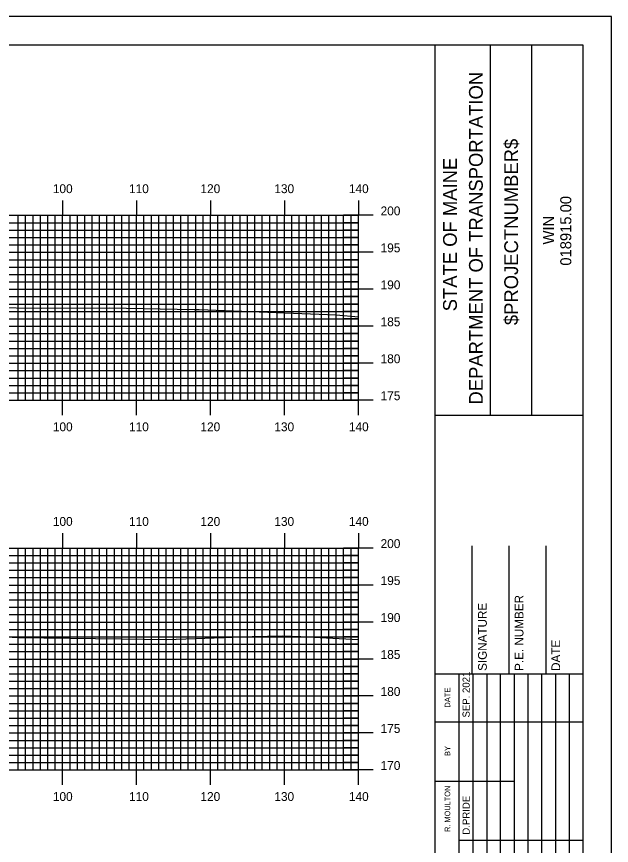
# Model space of a CAD drawing. Extents: x 1797207 to 1797550, y 442591 to 442811.
# Drawn here: x 1797466.7 to 1797547.1, y 442698.5 to 442810.5 of the extents above; entities that cross this region are included whole.
import ezdxf

# ---------------------------------------------------------------- set-up
doc = ezdxf.new("R2010")
doc.units = 0
for name, color, linetype in [('BORDER', 7, 'Continuous'), ('H_V ANNOTATION', 7, 'Continuous'), ('MAJOR', 7, 'Continuous'), ('MINOR', 7, 'Continuous'), ('PLOT BOUNDARY', 7, 'Continuous'), ('S_Roadway_Centerline', 7, 'Continuous')]:
    doc.layers.add(name, color=color, linetype=linetype)

msp = doc.modelspace()

# ---------------------------------------------------------------- linework, layer by layer
at = {"layer": 'BORDER'}
for p, q in [((1797523.33, 442596.67), (1797523.33, 442806.67)), ((1797530.79, 442756.66), (1797530.79, 442806.66)), ((1797536.38, 442756.66), (1797536.38, 442806.66)), ((1797523.33, 442756.65), (1797543.33, 442756.65)), ((1797528.33, 442721.67), (1797528.33, 442738.97)), ((1797533.33, 442721.67), (1797533.33, 442738.97)), ((1797538.33, 442721.67), (1797538.33, 442738.97)), ((1797523.33, 442721.67), (1797543.33, 442721.67))]:
    msp.add_line(p, q, dxfattribs=at)
msp.add_lwpolyline([(1797223.33, 442596.67), (1797543.33, 442596.67), (1797543.33, 442806.67), (1797223.33, 442806.67)], close=True, dxfattribs=at)
for points in [[(1797526.56, 442715.17), (1797526.56, 442721.67)], [(1797528.43, 442686.68), (1797528.43, 442721.67)], [(1797530.29, 442721.67), (1797530.29, 442686.68)], [(1797532.15, 442686.68), (1797532.15, 442721.67)], [(1797534.02, 442686.68), (1797534.02, 442721.67)], [(1797535.88, 442686.68), (1797535.88, 442721.67)], [(1797537.74, 442686.68), (1797537.74, 442721.67)], [(1797539.61, 442686.68), (1797539.61, 442721.67)], [(1797541.47, 442686.68), (1797541.47, 442721.67)], [(1797526.56, 442686.68), (1797526.56, 442720.26)], [(1797523.33, 442715.17), (1797543.33, 442715.17)], [(1797523.33, 442707.17), (1797526.56, 442707.17)], [(1797526.56, 442707.17), (1797534.01, 442707.17)], [(1797526.56, 442699.17), (1797543.33, 442699.17)]]:
    msp.add_lwpolyline(points, dxfattribs=at)
at = {"layer": 'MAJOR'}
for p, q in [((1797472.93, 442785.67), (1797472.93, 442783.67)), ((1797482.93, 442785.67), (1797482.93, 442783.67)), ((1797492.93, 442785.67), (1797492.93, 442783.67)), ((1797502.93, 442785.67), (1797502.93, 442783.67)), ((1797512.93, 442785.67), (1797512.93, 442783.67)), ((1797232.93, 442783.67), (1797512.93, 442783.67)), ((1797232.93, 442783.67), (1797512.93, 442783.67)), ((1797472.93, 442758.67), (1797472.93, 442783.67)), ((1797482.93, 442758.67), (1797482.93, 442783.67)), ((1797492.93, 442758.67), (1797492.93, 442783.67)), ((1797502.93, 442758.67), (1797502.93, 442783.67)), ((1797514.94, 442783.67), (1797510.93, 442783.67)), ((1797512.93, 442758.67), (1797512.93, 442783.67)), ((1797512.93, 442758.67), (1797512.93, 442783.67)), ((1797232.93, 442778.67), (1797512.93, 442778.67)), ((1797514.94, 442778.67), (1797510.93, 442778.67)), ((1797232.93, 442773.67), (1797512.93, 442773.67)), ((1797514.94, 442773.67), (1797510.93, 442773.67)), ((1797232.93, 442768.67), (1797512.93, 442768.67)), ((1797514.94, 442768.67), (1797510.93, 442768.67)), ((1797232.93, 442763.67), (1797512.93, 442763.67)), ((1797514.94, 442763.67), (1797510.93, 442763.67)), ((1797232.93, 442758.67), (1797512.93, 442758.67)), ((1797232.93, 442758.67), (1797512.93, 442758.67)), ((1797472.93, 442756.66), (1797472.93, 442758.67)), ((1797482.93, 442756.66), (1797482.93, 442758.67)), ((1797492.93, 442756.66), (1797492.93, 442758.67)), ((1797502.93, 442756.66), (1797502.93, 442758.67)), ((1797514.94, 442758.67), (1797510.93, 442758.67)), ((1797512.93, 442756.66), (1797512.93, 442758.67)), ((1797472.93, 442740.67), (1797472.93, 442738.67)), ((1797482.93, 442740.67), (1797482.93, 442738.67)), ((1797492.93, 442740.67), (1797492.93, 442738.67)), ((1797502.93, 442740.67), (1797502.93, 442738.67)), ((1797512.93, 442740.67), (1797512.93, 442738.67)), ((1797232.93, 442738.67), (1797512.93, 442738.67)), ((1797232.93, 442738.67), (1797512.93, 442738.67)), ((1797472.93, 442708.67), (1797472.93, 442738.67)), ((1797482.93, 442708.67), (1797482.93, 442738.67)), ((1797492.93, 442708.67), (1797492.93, 442738.67)), ((1797502.93, 442708.67), (1797502.93, 442738.67)), ((1797514.94, 442738.67), (1797510.93, 442738.67)), ((1797512.93, 442708.67), (1797512.93, 442738.67)), ((1797512.93, 442708.67), (1797512.93, 442738.67)), ((1797232.93, 442733.67), (1797512.93, 442733.67)), ((1797514.94, 442733.67), (1797510.93, 442733.67)), ((1797232.93, 442728.67), (1797512.93, 442728.67)), ((1797514.94, 442728.67), (1797510.93, 442728.67)), ((1797232.93, 442723.67), (1797512.93, 442723.67)), ((1797514.94, 442723.67), (1797510.93, 442723.67)), ((1797232.93, 442718.67), (1797512.93, 442718.67)), ((1797514.94, 442718.67), (1797510.93, 442718.67)), ((1797232.93, 442713.67), (1797512.93, 442713.67)), ((1797514.94, 442713.67), (1797510.93, 442713.67)), ((1797232.93, 442708.67), (1797512.93, 442708.67)), ((1797232.93, 442708.67), (1797512.93, 442708.67)), ((1797472.93, 442706.66), (1797472.93, 442708.67)), ((1797482.93, 442706.66), (1797482.93, 442708.67)), ((1797492.93, 442706.66), (1797492.93, 442708.67)), ((1797502.93, 442706.66), (1797502.93, 442708.67)), ((1797514.94, 442708.67), (1797510.93, 442708.67)), ((1797512.93, 442706.66), (1797512.93, 442708.67))]:
    msp.add_line(p, q, dxfattribs=at)
at = {"layer": 'MINOR'}
for p, q in [((1797466.93, 442758.67), (1797466.93, 442783.67)), ((1797467.93, 442758.67), (1797467.93, 442783.67)), ((1797468.93, 442758.67), (1797468.93, 442783.67)), ((1797469.93, 442758.67), (1797469.93, 442783.67)), ((1797470.93, 442758.67), (1797470.93, 442783.67)), ((1797471.93, 442758.67), (1797471.93, 442783.67)), ((1797473.93, 442758.67), (1797473.93, 442783.67)), ((1797474.93, 442758.67), (1797474.93, 442783.67)), ((1797475.93, 442758.67), (1797475.93, 442783.67)), ((1797476.93, 442758.67), (1797476.93, 442783.67)), ((1797477.93, 442758.67), (1797477.93, 442783.67)), ((1797478.93, 442758.67), (1797478.93, 442783.67)), ((1797479.93, 442758.67), (1797479.93, 442783.67)), ((1797480.93, 442758.67), (1797480.93, 442783.67)), ((1797481.93, 442758.67), (1797481.93, 442783.67)), ((1797483.93, 442758.67), (1797483.93, 442783.67)), ((1797484.93, 442758.67), (1797484.93, 442783.67)), ((1797485.93, 442758.67), (1797485.93, 442783.67)), ((1797486.93, 442758.67), (1797486.93, 442783.67)), ((1797487.93, 442758.67), (1797487.93, 442783.67)), ((1797488.93, 442758.67), (1797488.93, 442783.67)), ((1797489.93, 442758.67), (1797489.93, 442783.67)), ((1797490.93, 442758.67), (1797490.93, 442783.67)), ((1797491.93, 442758.67), (1797491.93, 442783.67)), ((1797493.93, 442758.67), (1797493.93, 442783.67)), ((1797494.93, 442758.67), (1797494.93, 442783.67)), ((1797495.93, 442758.67), (1797495.93, 442783.67)), ((1797496.93, 442758.67), (1797496.93, 442783.67)), ((1797497.93, 442758.67), (1797497.93, 442783.67)), ((1797498.93, 442758.67), (1797498.93, 442783.67)), ((1797499.93, 442758.67), (1797499.93, 442783.67)), ((1797500.93, 442758.67), (1797500.93, 442783.67)), ((1797501.93, 442758.67), (1797501.93, 442783.67)), ((1797503.93, 442758.67), (1797503.93, 442783.67)), ((1797504.93, 442758.67), (1797504.93, 442783.67)), ((1797505.93, 442758.67), (1797505.93, 442783.67)), ((1797506.93, 442758.67), (1797506.93, 442783.67)), ((1797507.93, 442758.67), (1797507.93, 442783.67)), ((1797508.93, 442758.67), (1797508.93, 442783.67)), ((1797509.93, 442758.67), (1797509.93, 442783.67)), ((1797510.93, 442758.67), (1797510.93, 442783.67)), ((1797511.93, 442758.67), (1797511.93, 442783.67)), ((1797232.93, 442782.67), (1797512.93, 442782.67)), ((1797512.93, 442782.67), (1797510.93, 442782.67)), ((1797232.93, 442781.67), (1797512.93, 442781.67)), ((1797232.93, 442780.67), (1797512.93, 442780.67)), ((1797512.93, 442781.67), (1797510.93, 442781.67)), ((1797512.93, 442780.67), (1797510.93, 442780.67)), ((1797232.93, 442779.67), (1797512.93, 442779.67)), ((1797512.93, 442779.67), (1797510.93, 442779.67)), ((1797232.93, 442777.67), (1797512.93, 442777.67)), ((1797512.93, 442777.67), (1797510.93, 442777.67)), ((1797232.93, 442776.67), (1797512.93, 442776.67)), ((1797512.93, 442776.67), (1797510.93, 442776.67)), ((1797232.93, 442775.67), (1797512.93, 442775.67)), ((1797512.93, 442775.67), (1797510.93, 442775.67)), ((1797232.93, 442774.67), (1797512.93, 442774.67)), ((1797512.93, 442774.67), (1797510.93, 442774.67)), ((1797232.93, 442772.67), (1797512.93, 442772.67)), ((1797512.93, 442772.67), (1797510.93, 442772.67)), ((1797232.93, 442771.67), (1797512.93, 442771.67)), ((1797232.93, 442770.67), (1797512.93, 442770.67)), ((1797512.93, 442771.67), (1797510.93, 442771.67)), ((1797512.93, 442770.67), (1797510.93, 442770.67)), ((1797232.93, 442769.67), (1797512.93, 442769.67)), ((1797512.93, 442769.67), (1797510.93, 442769.67)), ((1797232.93, 442767.67), (1797512.93, 442767.67)), ((1797512.93, 442767.67), (1797510.93, 442767.67)), ((1797232.93, 442766.67), (1797512.93, 442766.67)), ((1797512.93, 442766.67), (1797510.93, 442766.67)), ((1797232.93, 442765.67), (1797512.93, 442765.67)), ((1797512.93, 442765.67), (1797510.93, 442765.67)), ((1797232.93, 442764.67), (1797512.93, 442764.67)), ((1797512.93, 442764.67), (1797510.93, 442764.67)), ((1797232.93, 442762.67), (1797512.93, 442762.67)), ((1797232.93, 442761.67), (1797512.93, 442761.67)), ((1797512.93, 442762.67), (1797510.93, 442762.67)), ((1797512.93, 442761.67), (1797510.93, 442761.67)), ((1797232.93, 442760.67), (1797512.93, 442760.67)), ((1797512.93, 442760.67), (1797510.93, 442760.67)), ((1797232.93, 442759.67), (1797512.93, 442759.67)), ((1797512.93, 442759.67), (1797510.93, 442759.67)), ((1797466.93, 442708.67), (1797466.93, 442738.67)), ((1797467.93, 442708.67), (1797467.93, 442738.67)), ((1797468.93, 442708.67), (1797468.93, 442738.67)), ((1797469.93, 442708.67), (1797469.93, 442738.67)), ((1797470.93, 442708.67), (1797470.93, 442738.67)), ((1797471.93, 442708.67), (1797471.93, 442738.67)), ((1797473.93, 442708.67), (1797473.93, 442738.67)), ((1797474.93, 442708.67), (1797474.93, 442738.67)), ((1797475.93, 442708.67), (1797475.93, 442738.67)), ((1797476.93, 442708.67), (1797476.93, 442738.67)), ((1797477.93, 442708.67), (1797477.93, 442738.67)), ((1797478.93, 442708.67), (1797478.93, 442738.67)), ((1797479.93, 442708.67), (1797479.93, 442738.67)), ((1797480.93, 442708.67), (1797480.93, 442738.67)), ((1797481.93, 442708.67), (1797481.93, 442738.67)), ((1797483.93, 442708.67), (1797483.93, 442738.67)), ((1797484.93, 442708.67), (1797484.93, 442738.67)), ((1797485.93, 442708.67), (1797485.93, 442738.67)), ((1797486.93, 442708.67), (1797486.93, 442738.67)), ((1797487.93, 442708.67), (1797487.93, 442738.67)), ((1797488.93, 442708.67), (1797488.93, 442738.67)), ((1797489.93, 442708.67), (1797489.93, 442738.67)), ((1797490.93, 442708.67), (1797490.93, 442738.67)), ((1797491.93, 442708.67), (1797491.93, 442738.67)), ((1797493.93, 442708.67), (1797493.93, 442738.67)), ((1797494.93, 442708.67), (1797494.93, 442738.67)), ((1797495.93, 442708.67), (1797495.93, 442738.67)), ((1797496.93, 442708.67), (1797496.93, 442738.67)), ((1797497.93, 442708.67), (1797497.93, 442738.67)), ((1797498.93, 442708.67), (1797498.93, 442738.67)), ((1797499.93, 442708.67), (1797499.93, 442738.67)), ((1797500.93, 442708.67), (1797500.93, 442738.67)), ((1797501.93, 442708.67), (1797501.93, 442738.67)), ((1797503.93, 442708.67), (1797503.93, 442738.67)), ((1797504.93, 442708.67), (1797504.93, 442738.67)), ((1797505.93, 442708.67), (1797505.93, 442738.67)), ((1797506.93, 442708.67), (1797506.93, 442738.67)), ((1797507.93, 442708.67), (1797507.93, 442738.67)), ((1797508.93, 442708.67), (1797508.93, 442738.67)), ((1797509.93, 442708.67), (1797509.93, 442738.67)), ((1797510.93, 442708.67), (1797510.93, 442738.67)), ((1797511.93, 442708.67), (1797511.93, 442738.67)), ((1797232.93, 442737.67), (1797512.93, 442737.67)), ((1797512.93, 442737.67), (1797510.93, 442737.67)), ((1797232.93, 442736.67), (1797512.93, 442736.67)), ((1797512.93, 442736.67), (1797510.93, 442736.67)), ((1797232.93, 442735.67), (1797512.93, 442735.67)), ((1797512.93, 442735.67), (1797510.93, 442735.67)), ((1797232.93, 442734.67), (1797512.93, 442734.67)), ((1797512.93, 442734.67), (1797510.93, 442734.67)), ((1797232.93, 442732.67), (1797512.93, 442732.67)), ((1797512.93, 442732.67), (1797510.93, 442732.67)), ((1797232.93, 442731.67), (1797512.93, 442731.67)), ((1797512.93, 442731.67), (1797510.93, 442731.67)), ((1797232.93, 442730.67), (1797512.93, 442730.67)), ((1797512.93, 442730.67), (1797510.93, 442730.67)), ((1797232.93, 442729.67), (1797512.93, 442729.67)), ((1797512.93, 442729.67), (1797510.93, 442729.67)), ((1797232.93, 442727.67), (1797512.93, 442727.67)), ((1797512.93, 442727.67), (1797510.93, 442727.67)), ((1797232.93, 442726.67), (1797512.93, 442726.67)), ((1797512.93, 442726.67), (1797510.93, 442726.67)), ((1797232.93, 442725.67), (1797512.93, 442725.67)), ((1797232.93, 442724.67), (1797512.93, 442724.67)), ((1797512.93, 442725.67), (1797510.93, 442725.67)), ((1797512.93, 442724.67), (1797510.93, 442724.67)), ((1797232.93, 442722.67), (1797512.93, 442722.67)), ((1797512.93, 442722.67), (1797510.93, 442722.67)), ((1797232.93, 442721.67), (1797512.93, 442721.67)), ((1797512.93, 442721.67), (1797510.93, 442721.67)), ((1797232.93, 442720.67), (1797512.93, 442720.67)), ((1797512.93, 442720.67), (1797510.93, 442720.67)), ((1797232.93, 442719.67), (1797512.93, 442719.67)), ((1797512.93, 442719.67), (1797510.93, 442719.67)), ((1797232.93, 442717.67), (1797512.93, 442717.67)), ((1797512.93, 442717.67), (1797510.93, 442717.67)), ((1797232.93, 442716.67), (1797512.93, 442716.67)), ((1797232.93, 442715.67), (1797512.93, 442715.67)), ((1797512.93, 442716.67), (1797510.93, 442716.67)), ((1797512.93, 442715.67), (1797510.93, 442715.67)), ((1797232.93, 442714.67), (1797512.93, 442714.67)), ((1797512.93, 442714.67), (1797510.93, 442714.67)), ((1797232.93, 442712.67), (1797512.93, 442712.67)), ((1797512.93, 442712.67), (1797510.93, 442712.67)), ((1797232.93, 442711.67), (1797512.93, 442711.67)), ((1797512.93, 442711.67), (1797510.93, 442711.67)), ((1797232.93, 442710.67), (1797512.93, 442710.67)), ((1797512.93, 442710.67), (1797510.93, 442710.67)), ((1797232.93, 442709.67), (1797512.93, 442709.67)), ((1797512.93, 442709.67), (1797510.93, 442709.67))]:
    msp.add_line(p, q, dxfattribs=at)
at = {"layer": 'PLOT BOUNDARY'}
msp.add_lwpolyline([(1797207.14, 442590.55), (1797547.14, 442590.55), (1797547.14, 442810.55), (1797207.14, 442810.55)], close=True, dxfattribs=at)
at = {"layer": 'S_Roadway_Centerline'}
for points in [[(1797463.24, 442771.2), (1797470.07, 442771.1), (1797479.25, 442771.18), (1797490.72, 442770.95), (1797491.4, 442770.94), (1797509.94, 442770.2), (1797512.93, 442769.94)], [(1797461.14, 442726.89), (1797466.94, 442726.6), (1797480.86, 442726.41), (1797487.04, 442726.31), (1797498.55, 442726.73), (1797502.7, 442726.79), (1797505.16, 442726.7), (1797512.93, 442726.32)]]:
    msp.add_lwpolyline(points, dxfattribs=at)

# ---------------------------------------------------------------- texts
at = {"layer": 'BORDER'}
for s, height, p in [('DEPARTMENT OF TRANSPORTATION', 1.8635, (1797529.75, 442758.08)), ('$PROJECTNUMBER$', 1.8635, (1797534.52, 442768.82)), ('STATE OF MAINE', 1.8635, (1797526.24, 442770.69)), ('018915.00', 1.491, (1797541.72, 442776.86)), ('WIN', 1.491, (1797539.4, 442779.73)), ('P.E. NUMBER', 1.1811, (1797535.25, 442722.06)), ('SIGNATURE', 1.181, (1797530.29, 442722.06)), ('DATE', 1.181, (1797540.21, 442722.06)), ('SEP. 2021', 0.969, (1797527.98, 442715.76)), ('DATE', 0.743, (1797525.34, 442717.08)), ('BY', 0.743, (1797525.34, 442710.54)), ('R. MOULTON', 0.745, (1797525.34, 442700.28)), ('D.PRIDE', 0.969, (1797527.98, 442699.92))]:
    msp.add_text(s, height=height, rotation=90, dxfattribs=at).set_placement(p)
at = {"layer": 'H_V ANNOTATION'}
for s, p in [('100', (1797471.61, 442786.67)), ('110', (1797481.91, 442786.67)), ('120', (1797491.57, 442786.67)), ('130', (1797501.56, 442786.67)), ('140', (1797511.64, 442786.67)), ('200', (1797515.93, 442783.67)), ('195', (1797515.93, 442778.67)), ('190', (1797515.93, 442773.67)), ('185', (1797515.93, 442768.67)), ('180', (1797515.93, 442763.67)), ('175', (1797515.93, 442758.67)), ('100', (1797471.61, 442754.47)), ('110', (1797481.91, 442754.47)), ('120', (1797491.57, 442754.47)), ('130', (1797501.56, 442754.47)), ('140', (1797511.64, 442754.47)), ('100', (1797471.61, 442741.67)), ('110', (1797481.91, 442741.67)), ('120', (1797491.57, 442741.67)), ('130', (1797501.56, 442741.67)), ('140', (1797511.64, 442741.67)), ('200', (1797515.93, 442738.67)), ('195', (1797515.93, 442733.67)), ('190', (1797515.93, 442728.67)), ('185', (1797515.93, 442723.67)), ('180', (1797515.93, 442718.67)), ('175', (1797515.93, 442713.67)), ('170', (1797515.93, 442708.67)), ('100', (1797471.61, 442704.47)), ('110', (1797481.91, 442704.47)), ('120', (1797491.57, 442704.47)), ('130', (1797501.56, 442704.47)), ('140', (1797511.64, 442704.47))]:
    msp.add_text(s, height=1.2, dxfattribs=at).set_placement(p)

doc.saveas('drawing.dxf')
